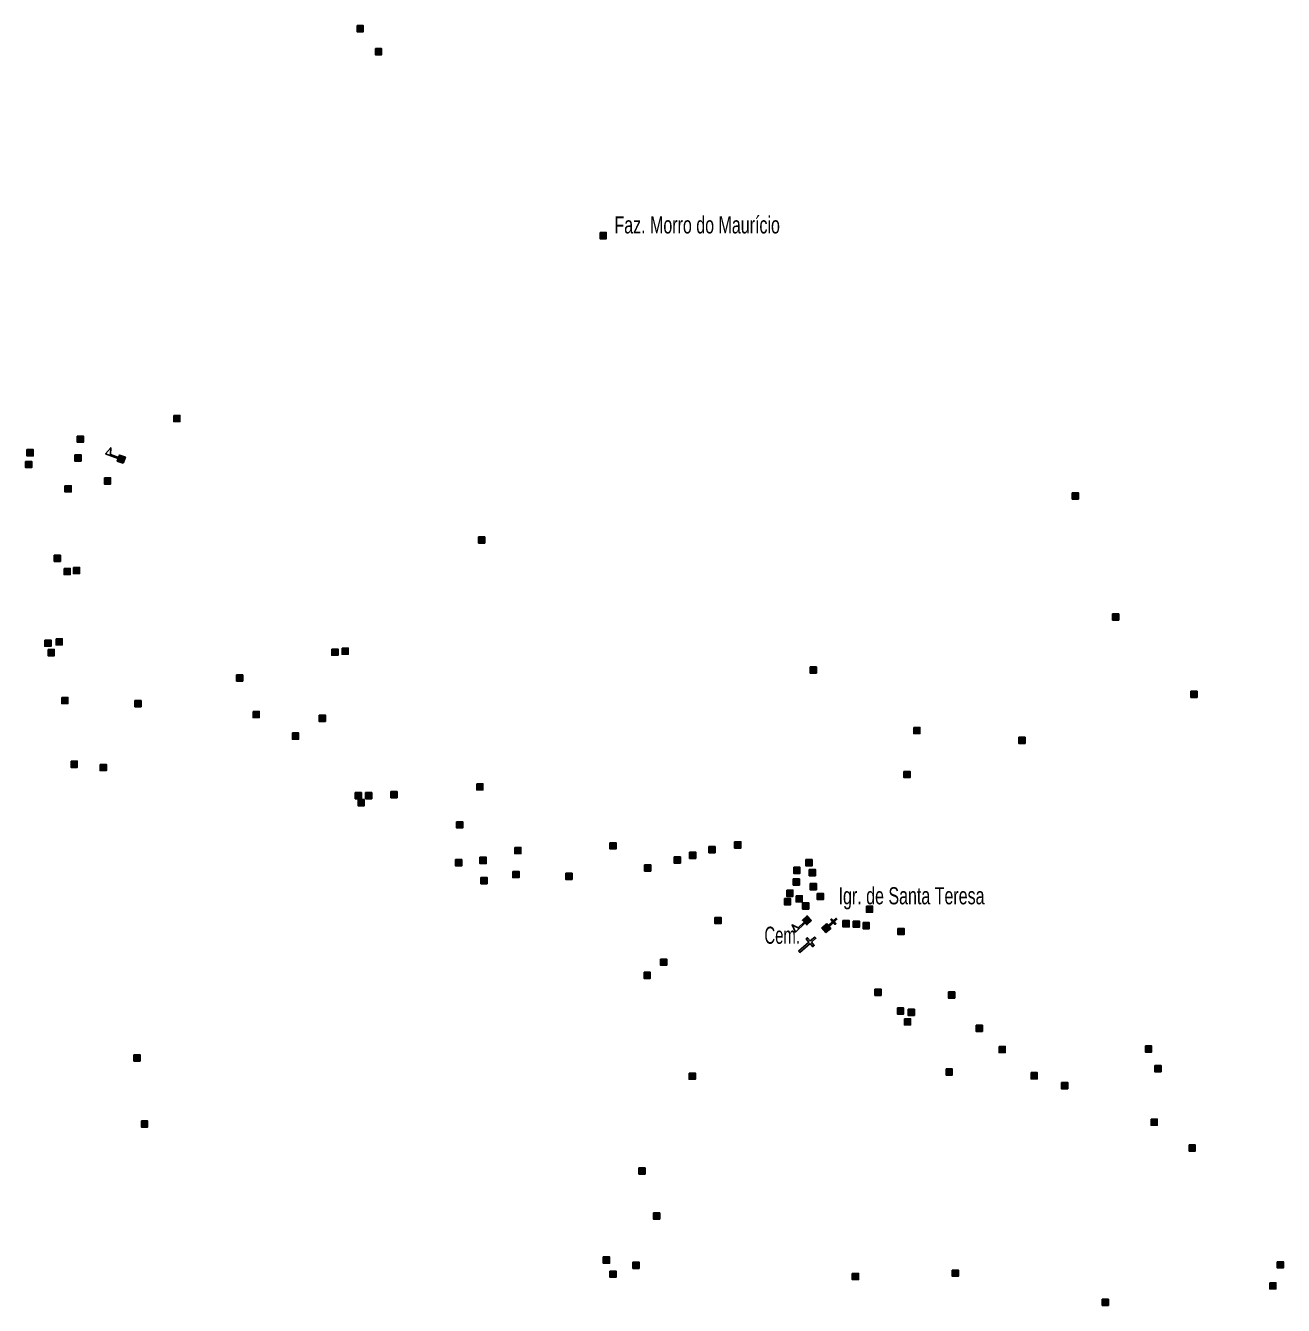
# Model space of a CAD drawing. Extents: x 647.8 to 672.9, y 6929.3 to 6957.3.
# Drawn here: x 654.04 to 659.92, y 6937.17 to 6943.15 of the extents above; entities that cross this region are included whole.
import ezdxf
from ezdxf.enums import TextEntityAlignment as Align

# ---------------------------------------------------------------- set-up
doc = ezdxf.new("R2010")
doc.units = 0
doc.header["$LTSCALE"] = 0.032
for name, color, linetype, lineweight in [('2', 7, 'Continuous', 25), ('20', 7, 'Continuous', 25), ('4', 7, 'Continuous', 25), ('6', 7, 'Continuous', 25)]:
    doc.layers.add(name, color=color, linetype=linetype, lineweight=lineweight)
doc.layers.add('61', color=7, linetype='Continuous')

msp = doc.modelspace()

# ---------------------------------------------------------------- hatches: boundary and pattern name
at = {"layer": '2'}
for points in [[(655.588, 6943.1522), (655.617, 6943.1522), (655.617, 6943.1232), (655.588, 6943.1232)], [(655.6736, 6943.0447), (655.7026, 6943.0447), (655.7026, 6943.0157), (655.6736, 6943.0157)], [(656.7245, 6942.1847), (656.7535, 6942.1847), (656.7535, 6942.1557), (656.7245, 6942.1557)], [(654.7302, 6941.3291), (654.7592, 6941.3291), (654.7592, 6941.3001), (654.7302, 6941.3001)], [(654.2783, 6941.2326), (654.3073, 6941.2326), (654.3073, 6941.2036), (654.2783, 6941.2036)], [(654.0436, 6941.169), (654.0726, 6941.169), (654.0726, 6941.14), (654.0436, 6941.14)], [(654.037, 6941.1141), (654.066, 6941.1141), (654.066, 6941.0851), (654.037, 6941.0851)], [(654.2673, 6941.1448), (654.2963, 6941.1448), (654.2963, 6941.1158), (654.2673, 6941.1158)], [(654.4056, 6941.0373), (654.4346, 6941.0373), (654.4346, 6941.0083), (654.4056, 6941.0083)], [(654.2213, 6941), (654.2503, 6941), (654.2503, 6940.971), (654.2213, 6940.971)], [(658.9337, 6940.9671), (658.9627, 6940.9671), (658.9627, 6940.9381), (658.9337, 6940.9381)], [(656.1562, 6940.7609), (656.1852, 6940.7609), (656.1852, 6940.7319), (656.1562, 6940.7319)], [(654.1708, 6940.6754), (654.1998, 6940.6754), (654.1998, 6940.6464), (654.1708, 6940.6464)], [(654.2169, 6940.6139), (654.2459, 6940.6139), (654.2459, 6940.5849), (654.2169, 6940.5849)], [(654.2608, 6940.6183), (654.2898, 6940.6183), (654.2898, 6940.5893), (654.2608, 6940.5893)], [(659.1223, 6940.4011), (659.1513, 6940.4011), (659.1513, 6940.3721), (659.1223, 6940.3721)], [(654.1269, 6940.2783), (654.1559, 6940.2783), (654.1559, 6940.2493), (654.1269, 6940.2493)], [(654.1796, 6940.2848), (654.2086, 6940.2848), (654.2086, 6940.2558), (654.1796, 6940.2558)], [(654.1423, 6940.2344), (654.1713, 6940.2344), (654.1713, 6940.2054), (654.1423, 6940.2054)], [(655.4696, 6940.2366), (655.4986, 6940.2366), (655.4986, 6940.2076), (655.4696, 6940.2076)], [(655.5178, 6940.241), (655.5468, 6940.241), (655.5468, 6940.212), (655.5178, 6940.212)], [(657.7073, 6940.1532), (657.7363, 6940.1532), (657.7363, 6940.1242), (657.7073, 6940.1242)], [(655.0242, 6940.1159), (655.0532, 6940.1159), (655.0532, 6940.0869), (655.0242, 6940.0869)], [(659.4887, 6940.0391), (659.5177, 6940.0391), (659.5177, 6940.0101), (659.4887, 6940.0101)], [(654.2059, 6940.0106), (654.2349, 6940.0106), (654.2349, 6939.9816), (654.2059, 6939.9816)], [(654.5482, 6939.9953), (654.5772, 6939.9953), (654.5772, 6939.9663), (654.5482, 6939.9663)], [(655.101, 6939.9448), (655.13, 6939.9448), (655.13, 6939.9158), (655.101, 6939.9158)], [(655.4103, 6939.9273), (655.4393, 6939.9273), (655.4393, 6939.8983), (655.4103, 6939.8983)], [(655.2853, 6939.8439), (655.3143, 6939.8439), (655.3143, 6939.8149), (655.2853, 6939.8149)], [(658.1921, 6939.8702), (658.2211, 6939.8702), (658.2211, 6939.8412), (658.1921, 6939.8412)], [(658.6836, 6939.8241), (658.7126, 6939.8241), (658.7126, 6939.7951), (658.6836, 6939.7951)], [(654.2498, 6939.7123), (654.2788, 6939.7123), (654.2788, 6939.6833), (654.2498, 6939.6833)], [(654.3858, 6939.6969), (654.4148, 6939.6969), (654.4148, 6939.6679), (654.3858, 6939.6679)], [(658.1461, 6939.664), (658.1751, 6939.664), (658.1751, 6939.635), (658.1461, 6939.635)], [(656.1475, 6939.6069), (656.1765, 6939.6069), (656.1765, 6939.5779), (656.1475, 6939.5779)], [(655.5793, 6939.5653), (655.6083, 6939.5653), (655.6083, 6939.5363), (655.5793, 6939.5363)], [(655.6275, 6939.5653), (655.6565, 6939.5653), (655.6565, 6939.5363), (655.6275, 6939.5363)], [(655.746, 6939.5697), (655.775, 6939.5697), (655.775, 6939.5407), (655.746, 6939.5407)], [(655.5924, 6939.5324), (655.6214, 6939.5324), (655.6214, 6939.5034), (655.5924, 6939.5034)], [(656.0531, 6939.4292), (656.0821, 6939.4292), (656.0821, 6939.4002), (656.0531, 6939.4002)], [(656.3252, 6939.3086), (656.3542, 6939.3086), (656.3542, 6939.2796), (656.3252, 6939.2796)], [(656.7705, 6939.3305), (656.7995, 6939.3305), (656.7995, 6939.3015), (656.7705, 6939.3015)], [(657.2334, 6939.313), (657.2624, 6939.313), (657.2624, 6939.284), (657.2334, 6939.284)], [(657.3541, 6939.3349), (657.3831, 6939.3349), (657.3831, 6939.3059), (657.3541, 6939.3059)], [(656.0487, 6939.2515), (656.0777, 6939.2515), (656.0777, 6939.2225), (656.0487, 6939.2225)], [(656.1628, 6939.2625), (656.1918, 6939.2625), (656.1918, 6939.2335), (656.1628, 6939.2335)], [(657.0711, 6939.2647), (657.1001, 6939.2647), (657.1001, 6939.2357), (657.0711, 6939.2357)], [(657.1435, 6939.2866), (657.1725, 6939.2866), (657.1725, 6939.2576), (657.1435, 6939.2576)], [(657.6875, 6939.2515), (657.7165, 6939.2515), (657.7165, 6939.2225), (657.6875, 6939.2225)], [(656.3164, 6939.1967), (656.3454, 6939.1967), (656.3454, 6939.1677), (656.3164, 6939.1677)], [(656.5643, 6939.1879), (656.5933, 6939.1879), (656.5933, 6939.1589), (656.5643, 6939.1589)], [(656.9329, 6939.2274), (656.9619, 6939.2274), (656.9619, 6939.1984), (656.9329, 6939.1984)], [(657.6305, 6939.2164), (657.6595, 6939.2164), (657.6595, 6939.1874), (657.6305, 6939.1874)], [(657.7029, 6939.2055), (657.7319, 6939.2055), (657.7319, 6939.1765), (657.7029, 6939.1765)], [(656.1672, 6939.1682), (656.1962, 6939.1682), (656.1962, 6939.1392), (656.1672, 6939.1392)], [(657.6283, 6939.1616), (657.6573, 6939.1616), (657.6573, 6939.1326), (657.6283, 6939.1326)], [(657.7073, 6939.1397), (657.7363, 6939.1397), (657.7363, 6939.1107), (657.7073, 6939.1107)], [(657.5866, 6939.0695), (657.6156, 6939.0695), (657.6156, 6939.0405), (657.5866, 6939.0405)], [(657.5976, 6939.1089), (657.6266, 6939.1089), (657.6266, 6939.0799), (657.5976, 6939.0799)], [(657.6415, 6939.0826), (657.6705, 6939.0826), (657.6705, 6939.0536), (657.6415, 6939.0536)], [(657.7402, 6939.0936), (657.7692, 6939.0936), (657.7692, 6939.0646), (657.7402, 6939.0646)], [(657.6722, 6939.0497), (657.7012, 6939.0497), (657.7012, 6939.0207), (657.6722, 6939.0207)], [(657.9706, 6939.0344), (657.9996, 6939.0344), (657.9996, 6939.0054), (657.9706, 6939.0054)], [(657.2619, 6938.9817), (657.2909, 6938.9817), (657.2909, 6938.9527), (657.2619, 6938.9527)], [(657.8609, 6938.9663), (657.8899, 6938.9663), (657.8899, 6938.9373), (657.8609, 6938.9373)], [(657.9091, 6938.9642), (657.9381, 6938.9642), (657.9381, 6938.9352), (657.9091, 6938.9352)], [(657.9552, 6938.9576), (657.9842, 6938.9576), (657.9842, 6938.9286), (657.9552, 6938.9286)], [(658.1178, 6938.9302), (658.1468, 6938.9302), (658.1468, 6938.9012), (658.1178, 6938.9012)], [(657.0075, 6938.7865), (657.0365, 6938.7865), (657.0365, 6938.7575), (657.0075, 6938.7575)], [(656.9307, 6938.725), (656.9597, 6938.725), (656.9597, 6938.696), (656.9307, 6938.696)], [(658.01, 6938.646), (658.039, 6938.646), (658.039, 6938.617), (658.01, 6938.617)], [(658.3545, 6938.6329), (658.3835, 6938.6329), (658.3835, 6938.6039), (658.3545, 6938.6039)], [(658.1153, 6938.5583), (658.1443, 6938.5583), (658.1443, 6938.5293), (658.1153, 6938.5293)], [(658.1658, 6938.5517), (658.1948, 6938.5517), (658.1948, 6938.5227), (658.1658, 6938.5227)], [(658.1483, 6938.5078), (658.1773, 6938.5078), (658.1773, 6938.4788), (658.1483, 6938.4788)], [(658.4839, 6938.4771), (658.5129, 6938.4771), (658.5129, 6938.4481), (658.4839, 6938.4481)], [(658.5914, 6938.3784), (658.6204, 6938.3784), (658.6204, 6938.3494), (658.5914, 6938.3494)], [(659.2759, 6938.3806), (659.3049, 6938.3806), (659.3049, 6938.3516), (659.2759, 6938.3516)], [(654.5438, 6938.3389), (654.5728, 6938.3389), (654.5728, 6938.3099), (654.5438, 6938.3099)], [(659.3198, 6938.2884), (659.3488, 6938.2884), (659.3488, 6938.2594), (659.3198, 6938.2594)], [(657.1413, 6938.2533), (657.1703, 6938.2533), (657.1703, 6938.2243), (657.1413, 6938.2243)], [(658.3435, 6938.2731), (658.3725, 6938.2731), (658.3725, 6938.2441), (658.3435, 6938.2441)], [(658.7406, 6938.2555), (658.7696, 6938.2555), (658.7696, 6938.2265), (658.7406, 6938.2265)], [(658.8832, 6938.2095), (658.9122, 6938.2095), (658.9122, 6938.1805), (658.8832, 6938.1805)], [(654.5789, 6938.0296), (654.6079, 6938.0296), (654.6079, 6938.0006), (654.5789, 6938.0006)], [(659.3022, 6938.0383), (659.3312, 6938.0383), (659.3312, 6938.0093), (659.3022, 6938.0093)], [(659.4799, 6937.9177), (659.5089, 6937.9177), (659.5089, 6937.8887), (659.4799, 6937.8887)], [(656.9065, 6937.8102), (656.9355, 6937.8102), (656.9355, 6937.7812), (656.9065, 6937.7812)], [(656.9745, 6937.5996), (657.0035, 6937.5996), (657.0035, 6937.5706), (656.9745, 6937.5706)], [(656.7398, 6937.3934), (656.7688, 6937.3934), (656.7688, 6937.3644), (656.7398, 6937.3644)], [(656.7705, 6937.3275), (656.7995, 6937.3275), (656.7995, 6937.2985), (656.7705, 6937.2985)], [(656.878, 6937.3692), (656.907, 6937.3692), (656.907, 6937.3402), (656.878, 6937.3402)], [(658.372, 6937.3319), (658.401, 6937.3319), (658.401, 6937.3029), (658.372, 6937.3029)], [(659.8924, 6937.3714), (659.9214, 6937.3714), (659.9214, 6937.3424), (659.8924, 6937.3424)], [(657.9047, 6937.3166), (657.9337, 6937.3166), (657.9337, 6937.2876), (657.9047, 6937.2876)], [(659.8573, 6937.2727), (659.8863, 6937.2727), (659.8863, 6937.2437), (659.8573, 6937.2437)], [(659.0741, 6937.1959), (659.1031, 6937.1959), (659.1031, 6937.1669), (659.0741, 6937.1669)]]:
    msp.add_hatch(color=256, dxfattribs=at).paths.add_polyline_path(points)
at = {"layer": '4'}
for points in [[(654.4937, 6941.1053), (654.4657, 6941.1158), (654.4762, 6941.1439), (654.5043, 6941.1333)], [(657.714, 6938.9672), (657.6922, 6938.9466), (657.6715, 6938.9684), (657.6933, 6938.989)]]:
    msp.add_hatch(color=256, dxfattribs=at).paths.add_polyline_path(points)
at = {"layer": '6'}
for points in [[(657.7838, 6938.9525), (657.7615, 6938.9325), (657.7815, 6938.9101), (657.8038, 6938.9303)], [(657.7955, 6938.9396), (657.7922, 6938.9432), (657.8126, 6938.9617), (657.8042, 6938.971), (657.8079, 6938.9743), (657.8163, 6938.9651), (657.8293, 6938.9767), (657.8326, 6938.973), (657.8196, 6938.9613), (657.828, 6938.952), (657.8243, 6938.9486), (657.8159, 6938.9579)]]:
    msp.add_hatch(color=256, dxfattribs=at).paths.add_polyline_path(points)

# ---------------------------------------------------------------- linework, layer by layer
at = {"layer": '2'}
for points in [[(655.588, 6943.1522), (655.617, 6943.1522), (655.617, 6943.1232), (655.588, 6943.1232)], [(655.6736, 6943.0447), (655.7026, 6943.0447), (655.7026, 6943.0157), (655.6736, 6943.0157)], [(656.7245, 6942.1847), (656.7535, 6942.1847), (656.7535, 6942.1557), (656.7245, 6942.1557)], [(654.7302, 6941.3291), (654.7592, 6941.3291), (654.7592, 6941.3001), (654.7302, 6941.3001)], [(654.2783, 6941.2326), (654.3073, 6941.2326), (654.3073, 6941.2036), (654.2783, 6941.2036)], [(654.0436, 6941.169), (654.0726, 6941.169), (654.0726, 6941.14), (654.0436, 6941.14)], [(654.037, 6941.1141), (654.066, 6941.1141), (654.066, 6941.0851), (654.037, 6941.0851)], [(654.2673, 6941.1448), (654.2963, 6941.1448), (654.2963, 6941.1158), (654.2673, 6941.1158)], [(654.4056, 6941.0373), (654.4346, 6941.0373), (654.4346, 6941.0083), (654.4056, 6941.0083)], [(654.2213, 6941), (654.2503, 6941), (654.2503, 6940.971), (654.2213, 6940.971)], [(658.9337, 6940.9671), (658.9627, 6940.9671), (658.9627, 6940.9381), (658.9337, 6940.9381)], [(656.1562, 6940.7609), (656.1852, 6940.7609), (656.1852, 6940.7319), (656.1562, 6940.7319)], [(654.1708, 6940.6754), (654.1998, 6940.6754), (654.1998, 6940.6464), (654.1708, 6940.6464)], [(654.2169, 6940.6139), (654.2459, 6940.6139), (654.2459, 6940.5849), (654.2169, 6940.5849)], [(654.2608, 6940.6183), (654.2898, 6940.6183), (654.2898, 6940.5893), (654.2608, 6940.5893)], [(659.1223, 6940.4011), (659.1513, 6940.4011), (659.1513, 6940.3721), (659.1223, 6940.3721)], [(654.1269, 6940.2783), (654.1559, 6940.2783), (654.1559, 6940.2493), (654.1269, 6940.2493)], [(654.1796, 6940.2848), (654.2086, 6940.2848), (654.2086, 6940.2558), (654.1796, 6940.2558)], [(654.1423, 6940.2344), (654.1713, 6940.2344), (654.1713, 6940.2054), (654.1423, 6940.2054)], [(655.4696, 6940.2366), (655.4986, 6940.2366), (655.4986, 6940.2076), (655.4696, 6940.2076)], [(655.5178, 6940.241), (655.5468, 6940.241), (655.5468, 6940.212), (655.5178, 6940.212)], [(657.7073, 6940.1532), (657.7363, 6940.1532), (657.7363, 6940.1242), (657.7073, 6940.1242)], [(655.0242, 6940.1159), (655.0532, 6940.1159), (655.0532, 6940.0869), (655.0242, 6940.0869)], [(659.4887, 6940.0391), (659.5177, 6940.0391), (659.5177, 6940.0101), (659.4887, 6940.0101)], [(654.2059, 6940.0106), (654.2349, 6940.0106), (654.2349, 6939.9816), (654.2059, 6939.9816)], [(654.5482, 6939.9953), (654.5772, 6939.9953), (654.5772, 6939.9663), (654.5482, 6939.9663)], [(655.101, 6939.9448), (655.13, 6939.9448), (655.13, 6939.9158), (655.101, 6939.9158)], [(655.4103, 6939.9273), (655.4393, 6939.9273), (655.4393, 6939.8983), (655.4103, 6939.8983)], [(655.2853, 6939.8439), (655.3143, 6939.8439), (655.3143, 6939.8149), (655.2853, 6939.8149)], [(658.1921, 6939.8702), (658.2211, 6939.8702), (658.2211, 6939.8412), (658.1921, 6939.8412)], [(658.6836, 6939.8241), (658.7126, 6939.8241), (658.7126, 6939.7951), (658.6836, 6939.7951)], [(654.2498, 6939.7123), (654.2788, 6939.7123), (654.2788, 6939.6833), (654.2498, 6939.6833)], [(654.3858, 6939.6969), (654.4148, 6939.6969), (654.4148, 6939.6679), (654.3858, 6939.6679)], [(658.1461, 6939.664), (658.1751, 6939.664), (658.1751, 6939.635), (658.1461, 6939.635)], [(656.1475, 6939.6069), (656.1765, 6939.6069), (656.1765, 6939.5779), (656.1475, 6939.5779)], [(655.5793, 6939.5653), (655.6083, 6939.5653), (655.6083, 6939.5363), (655.5793, 6939.5363)], [(655.6275, 6939.5653), (655.6565, 6939.5653), (655.6565, 6939.5363), (655.6275, 6939.5363)], [(655.746, 6939.5697), (655.775, 6939.5697), (655.775, 6939.5407), (655.746, 6939.5407)], [(655.5924, 6939.5324), (655.6214, 6939.5324), (655.6214, 6939.5034), (655.5924, 6939.5034)], [(656.0531, 6939.4292), (656.0821, 6939.4292), (656.0821, 6939.4002), (656.0531, 6939.4002)], [(656.3252, 6939.3086), (656.3542, 6939.3086), (656.3542, 6939.2796), (656.3252, 6939.2796)], [(656.7705, 6939.3305), (656.7995, 6939.3305), (656.7995, 6939.3015), (656.7705, 6939.3015)], [(657.2334, 6939.313), (657.2624, 6939.313), (657.2624, 6939.284), (657.2334, 6939.284)], [(657.3541, 6939.3349), (657.3831, 6939.3349), (657.3831, 6939.3059), (657.3541, 6939.3059)], [(656.0487, 6939.2515), (656.0777, 6939.2515), (656.0777, 6939.2225), (656.0487, 6939.2225)], [(656.1628, 6939.2625), (656.1918, 6939.2625), (656.1918, 6939.2335), (656.1628, 6939.2335)], [(657.0711, 6939.2647), (657.1001, 6939.2647), (657.1001, 6939.2357), (657.0711, 6939.2357)], [(657.1435, 6939.2866), (657.1725, 6939.2866), (657.1725, 6939.2576), (657.1435, 6939.2576)], [(657.6875, 6939.2515), (657.7165, 6939.2515), (657.7165, 6939.2225), (657.6875, 6939.2225)], [(656.3164, 6939.1967), (656.3454, 6939.1967), (656.3454, 6939.1677), (656.3164, 6939.1677)], [(656.5643, 6939.1879), (656.5933, 6939.1879), (656.5933, 6939.1589), (656.5643, 6939.1589)], [(656.9329, 6939.2274), (656.9619, 6939.2274), (656.9619, 6939.1984), (656.9329, 6939.1984)], [(657.6305, 6939.2164), (657.6595, 6939.2164), (657.6595, 6939.1874), (657.6305, 6939.1874)], [(657.7029, 6939.2055), (657.7319, 6939.2055), (657.7319, 6939.1765), (657.7029, 6939.1765)], [(656.1672, 6939.1682), (656.1962, 6939.1682), (656.1962, 6939.1392), (656.1672, 6939.1392)], [(657.6283, 6939.1616), (657.6573, 6939.1616), (657.6573, 6939.1326), (657.6283, 6939.1326)], [(657.7073, 6939.1397), (657.7363, 6939.1397), (657.7363, 6939.1107), (657.7073, 6939.1107)], [(657.5866, 6939.0695), (657.6156, 6939.0695), (657.6156, 6939.0405), (657.5866, 6939.0405)], [(657.5976, 6939.1089), (657.6266, 6939.1089), (657.6266, 6939.0799), (657.5976, 6939.0799)], [(657.6415, 6939.0826), (657.6705, 6939.0826), (657.6705, 6939.0536), (657.6415, 6939.0536)], [(657.7402, 6939.0936), (657.7692, 6939.0936), (657.7692, 6939.0646), (657.7402, 6939.0646)], [(657.6722, 6939.0497), (657.7012, 6939.0497), (657.7012, 6939.0207), (657.6722, 6939.0207)], [(657.9706, 6939.0344), (657.9996, 6939.0344), (657.9996, 6939.0054), (657.9706, 6939.0054)], [(657.2619, 6938.9817), (657.2909, 6938.9817), (657.2909, 6938.9527), (657.2619, 6938.9527)], [(657.8609, 6938.9663), (657.8899, 6938.9663), (657.8899, 6938.9373), (657.8609, 6938.9373)], [(657.9091, 6938.9642), (657.9381, 6938.9642), (657.9381, 6938.9352), (657.9091, 6938.9352)], [(657.9552, 6938.9576), (657.9842, 6938.9576), (657.9842, 6938.9286), (657.9552, 6938.9286)], [(658.1178, 6938.9302), (658.1468, 6938.9302), (658.1468, 6938.9012), (658.1178, 6938.9012)], [(657.0075, 6938.7865), (657.0365, 6938.7865), (657.0365, 6938.7575), (657.0075, 6938.7575)], [(656.9307, 6938.725), (656.9597, 6938.725), (656.9597, 6938.696), (656.9307, 6938.696)], [(658.01, 6938.646), (658.039, 6938.646), (658.039, 6938.617), (658.01, 6938.617)], [(658.3545, 6938.6329), (658.3835, 6938.6329), (658.3835, 6938.6039), (658.3545, 6938.6039)], [(658.1153, 6938.5583), (658.1443, 6938.5583), (658.1443, 6938.5293), (658.1153, 6938.5293)], [(658.1658, 6938.5517), (658.1948, 6938.5517), (658.1948, 6938.5227), (658.1658, 6938.5227)], [(658.1483, 6938.5078), (658.1773, 6938.5078), (658.1773, 6938.4788), (658.1483, 6938.4788)], [(658.4839, 6938.4771), (658.5129, 6938.4771), (658.5129, 6938.4481), (658.4839, 6938.4481)], [(658.5914, 6938.3784), (658.6204, 6938.3784), (658.6204, 6938.3494), (658.5914, 6938.3494)], [(659.2759, 6938.3806), (659.3049, 6938.3806), (659.3049, 6938.3516), (659.2759, 6938.3516)], [(654.5438, 6938.3389), (654.5728, 6938.3389), (654.5728, 6938.3099), (654.5438, 6938.3099)], [(659.3198, 6938.2884), (659.3488, 6938.2884), (659.3488, 6938.2594), (659.3198, 6938.2594)], [(657.1413, 6938.2533), (657.1703, 6938.2533), (657.1703, 6938.2243), (657.1413, 6938.2243)], [(658.3435, 6938.2731), (658.3725, 6938.2731), (658.3725, 6938.2441), (658.3435, 6938.2441)], [(658.7406, 6938.2555), (658.7696, 6938.2555), (658.7696, 6938.2265), (658.7406, 6938.2265)], [(658.8832, 6938.2095), (658.9122, 6938.2095), (658.9122, 6938.1805), (658.8832, 6938.1805)], [(654.5789, 6938.0296), (654.6079, 6938.0296), (654.6079, 6938.0006), (654.5789, 6938.0006)], [(659.3022, 6938.0383), (659.3312, 6938.0383), (659.3312, 6938.0093), (659.3022, 6938.0093)], [(659.4799, 6937.9177), (659.5089, 6937.9177), (659.5089, 6937.8887), (659.4799, 6937.8887)], [(656.9065, 6937.8102), (656.9355, 6937.8102), (656.9355, 6937.7812), (656.9065, 6937.7812)], [(656.9745, 6937.5996), (657.0035, 6937.5996), (657.0035, 6937.5706), (656.9745, 6937.5706)], [(656.7398, 6937.3934), (656.7688, 6937.3934), (656.7688, 6937.3644), (656.7398, 6937.3644)], [(656.7705, 6937.3275), (656.7995, 6937.3275), (656.7995, 6937.2985), (656.7705, 6937.2985)], [(656.878, 6937.3692), (656.907, 6937.3692), (656.907, 6937.3402), (656.878, 6937.3402)], [(658.372, 6937.3319), (658.401, 6937.3319), (658.401, 6937.3029), (658.372, 6937.3029)], [(659.8924, 6937.3714), (659.9214, 6937.3714), (659.9214, 6937.3424), (659.8924, 6937.3424)], [(657.9047, 6937.3166), (657.9337, 6937.3166), (657.9337, 6937.2876), (657.9047, 6937.2876)], [(659.8573, 6937.2727), (659.8863, 6937.2727), (659.8863, 6937.2437), (659.8573, 6937.2437)], [(659.0741, 6937.1959), (659.1031, 6937.1959), (659.1031, 6937.1669), (659.0741, 6937.1669)]]:
    msp.add_lwpolyline(points, close=True, dxfattribs=at)
at = {"layer": '20'}
for points in [[(657.7078, 6938.8713), (657.6947, 6938.8864), (657.6883, 6938.8808), (657.7014, 6938.8657), (657.6536, 6938.8239)], [(657.7131, 6938.8653), (657.7342, 6938.8837), (657.7289, 6938.8897), (657.7078, 6938.8713)], [(657.6536, 6938.8239), (657.6589, 6938.8179), (657.7067, 6938.8597)], [(657.7067, 6938.8597), (657.7198, 6938.8446), (657.7262, 6938.8502), (657.7131, 6938.8653)]]:
    msp.add_lwpolyline(points, dxfattribs=at)
at = {"layer": '4'}
for p, q in [((654.47, 6941.1276), (654.4718, 6941.1322)), ((657.6836, 6938.9556), (657.6801, 6938.9593))]:
    msp.add_line(p, q, dxfattribs=at)
for points in [[(654.47, 6941.1276), (654.4115, 6941.1497), (654.4356, 6941.178), (654.4349, 6941.1462), (654.4718, 6941.1322)], [(654.4937, 6941.1053), (654.4657, 6941.1158), (654.4762, 6941.1439), (654.5043, 6941.1333)], [(657.6836, 6938.9556), (657.6381, 6938.9127), (657.6232, 6938.9467), (657.6514, 6938.9321), (657.6801, 6938.9593)], [(657.714, 6938.9672), (657.6922, 6938.9466), (657.6715, 6938.9684), (657.6933, 6938.989)]]:
    msp.add_lwpolyline(points, close=True, dxfattribs=at)
at = {"layer": '6'}
for points in [[(657.7838, 6938.9525), (657.7615, 6938.9325), (657.7815, 6938.9101), (657.8038, 6938.9303)], [(657.7955, 6938.9396), (657.7922, 6938.9432), (657.8126, 6938.9617), (657.8042, 6938.971), (657.8079, 6938.9743), (657.8163, 6938.9651), (657.8293, 6938.9767), (657.8326, 6938.973), (657.8196, 6938.9613), (657.828, 6938.952), (657.8243, 6938.9486), (657.8159, 6938.9579)]]:
    msp.add_lwpolyline(points, close=True, dxfattribs=at)

# ---------------------------------------------------------------- texts
at = {"layer": '61', "width": 0.7}
for s, p in [('Faz. Morro do Maurício', (656.7918, 6942.1802)), ('Igr. de Santa Teresa', (657.8404, 6939.0427))]:
    msp.add_text(s, height=0.08, dxfattribs=at).set_placement(p)
at = {"layer": '61', "width": 0.65}
msp.add_text('Cem.', height=0.08, dxfattribs=at).set_placement((657.6596, 6938.8581), align=Align.RIGHT)

doc.saveas('drawing.dxf')
